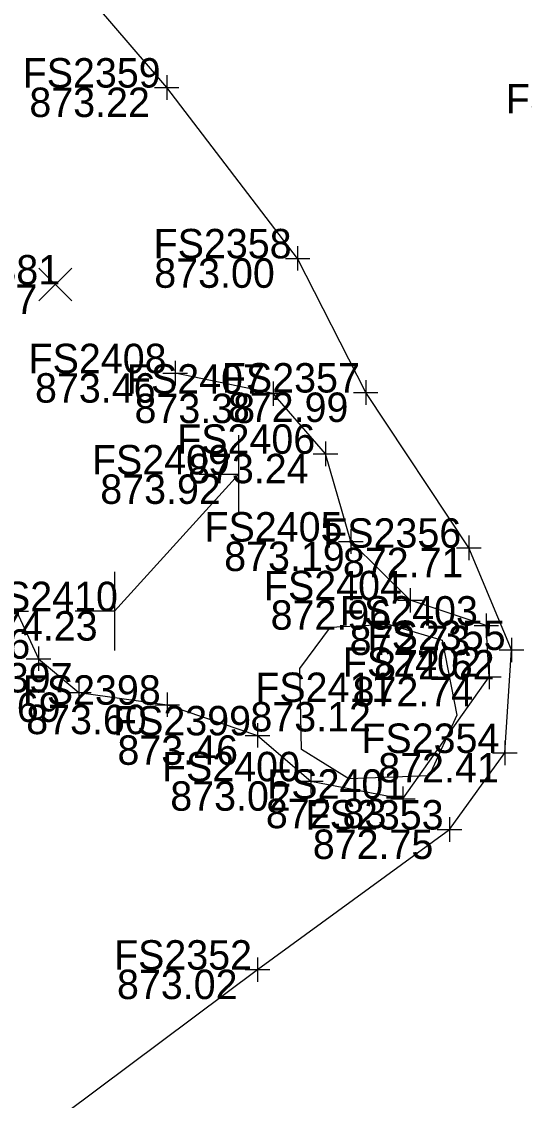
# Model space of a CAD drawing. Extents: x 1479420 to 1479833, y 379731 to 380103.
# Drawn here: x 1479533.91 to 1479554.39, y 379907.15 to 379951.11 of the extents above; entities that cross this region are included whole.
import ezdxf

# ---------------------------------------------------------------- set-up
doc = ezdxf.new("R2010")
doc.units = 0
for name, color, linetype in [('Default', 7, 'Continuous'), ('RD_X_Cells', 7, 'Continuous'), ('SN_X_Public', 7, 'Continuous'), ('SV_X_Break_Lines', 7, 'Continuous'), ('SV_X_Random_Point', 7, 'Continuous'), ('SV_X_Shot_Marker', 7, 'Continuous'), ('SV_X_Text_Elevation', 7, 'Continuous'), ('SV_X_Text_Name', 7, 'Continuous'), ('VG_X_Flower_Bed', 7, 'Continuous')]:
    doc.layers.add(name, color=color, linetype=linetype)

msp = doc.modelspace()

# ---------------------------------------------------------------- linework, layer by layer
at = {"layer": 'Default'}
msp.add_line((1479542.748, 379932.655), (1479537.693, 379927.083), dxfattribs=at)
at = {"layer": 'RD_X_Cells'}
msp.add_lwpolyline([(1479545.315, 379921.45), (1479545.24, 379924.75), (1479546.49, 379926.425), (1479548.84, 379926.55), (1479551.04, 379925.9), (1479551.64, 379922.85), (1479550.515, 379920.375), (1479547.24, 379920.25), (1479545.315, 379921.45)], dxfattribs=at)
at = {"layer": 'SN_X_Public'}
for p, q in [((1479542.748, 379934.255), (1479542.748, 379931.055)), ((1479542.748, 379932.655), (1479541.148, 379932.655)), ((1479537.693, 379928.683), (1479537.693, 379925.483)), ((1479537.693, 379927.083), (1479536.093, 379927.083))]:
    msp.add_line(p, q, dxfattribs=at)
at = {"layer": 'SV_X_Break_Lines'}
msp.add_lwpolyline([(1479534.387, 379905.648), (1479543.524, 379912.475), (1479551.336, 379918.185), (1479553.597, 379921.305), (1479553.861, 379925.501), (1479552.129, 379929.668), (1479547.926, 379935.993), (1479545.155, 379941.461), (1479539.822, 379948.42), (1479529.018, 379961.007), (1479520.635, 379970.728), (1479513.841, 379979.888), (1479504.809, 379988.776), (1479495.63, 379998.694), (1479487.89, 380006.933), (1479478.402, 380016.952), (1479472.872, 380022.536)], dxfattribs=at)
at = {"layer": 'SV_X_Random_Point'}
for p, q in [((1479534.619, 379939.728), (1479535.953, 379941.063)), ((1479534.619, 379941.063), (1479535.953, 379939.728))]:
    msp.add_line(p, q, dxfattribs=at)
at = {"layer": 'SV_X_Shot_Marker'}
for p, q in [((1479539.822, 379948.92), (1479539.822, 379947.92)), ((1479539.322, 379948.42), (1479540.322, 379948.42)), ((1479539.822, 379948.42), (1479539.822, 379948.42)), ((1479545.155, 379941.961), (1479545.155, 379940.961)), ((1479544.655, 379941.461), (1479545.655, 379941.461)), ((1479545.155, 379941.461), (1479545.155, 379941.461)), ((1479540.166, 379937.281), (1479540.166, 379936.281)), ((1479539.666, 379936.781), (1479540.666, 379936.781)), ((1479540.166, 379936.781), (1479540.166, 379936.781)), ((1479544.162, 379936.448), (1479544.162, 379935.448)), ((1479547.926, 379936.493), (1479547.926, 379935.493)), ((1479547.426, 379935.993), (1479548.426, 379935.993)), ((1479547.926, 379935.993), (1479547.926, 379935.993)), ((1479543.662, 379935.948), (1479544.662, 379935.948)), ((1479544.162, 379935.948), (1479544.162, 379935.948)), ((1479546.286, 379933.997), (1479546.286, 379932.997)), ((1479545.786, 379933.497), (1479546.786, 379933.497)), ((1479546.286, 379933.497), (1479546.286, 379933.497)), ((1479547.321, 379930.419), (1479547.321, 379929.419)), ((1479546.821, 379929.919), (1479547.821, 379929.919)), ((1479547.321, 379929.919), (1479547.321, 379929.919)), ((1479552.129, 379930.168), (1479552.129, 379929.168)), ((1479551.629, 379929.668), (1479552.629, 379929.668)), ((1479552.129, 379929.668), (1479552.129, 379929.668)), ((1479549.733, 379928.027), (1479549.733, 379927.027)), ((1479549.233, 379927.527), (1479550.233, 379927.527)), ((1479549.733, 379927.527), (1479549.733, 379927.527)), ((1479533.198, 379927.079), (1479534.198, 379927.079)), ((1479552.838, 379926.995), (1479552.838, 379925.995)), ((1479552.338, 379926.495), (1479553.338, 379926.495)), ((1479552.838, 379926.495), (1479552.838, 379926.495)), ((1479553.861, 379926.001), (1479553.861, 379925.001)), ((1479534.597, 379925.646), (1479534.597, 379924.646)), ((1479553.361, 379925.501), (1479554.361, 379925.501)), ((1479553.861, 379925.501), (1479553.861, 379925.501)), ((1479534.097, 379925.146), (1479535.097, 379925.146)), ((1479534.597, 379925.146), (1479534.597, 379925.146)), ((1479552.948, 379924.908), (1479552.948, 379923.908)), ((1479536.243, 379924.27), (1479536.243, 379923.27)), ((1479552.448, 379924.408), (1479553.448, 379924.408)), ((1479552.948, 379924.408), (1479552.948, 379924.408)), ((1479535.743, 379923.77), (1479536.743, 379923.77)), ((1479536.243, 379923.77), (1479536.243, 379923.77)), ((1479539.845, 379923.771), (1479539.845, 379922.771)), ((1479539.345, 379923.271), (1479540.345, 379923.271)), ((1479539.845, 379923.271), (1479539.845, 379923.271)), ((1479543.523, 379922.522), (1479543.523, 379921.522)), ((1479543.023, 379922.022), (1479544.023, 379922.022)), ((1479543.523, 379922.022), (1479543.523, 379922.022)), ((1479553.597, 379921.805), (1479553.597, 379920.805)), ((1479553.097, 379921.305), (1479554.097, 379921.305)), ((1479553.597, 379921.305), (1479553.597, 379921.305)), ((1479545.694, 379920.651), (1479545.694, 379919.651)), ((1479545.194, 379920.151), (1479546.194, 379920.151)), ((1479545.694, 379920.151), (1479545.694, 379920.151)), ((1479549.444, 379919.939), (1479549.444, 379918.939)), ((1479548.944, 379919.439), (1479549.944, 379919.439)), ((1479549.444, 379919.439), (1479549.444, 379919.439)), ((1479551.336, 379918.685), (1479551.336, 379917.685)), ((1479550.836, 379918.185), (1479551.836, 379918.185)), ((1479551.336, 379918.185), (1479551.336, 379918.185)), ((1479543.524, 379912.975), (1479543.524, 379911.975)), ((1479543.024, 379912.475), (1479544.024, 379912.475)), ((1479543.524, 379912.475), (1479543.524, 379912.475))]:
    msp.add_line(p, q, dxfattribs=at)
at = {"layer": 'VG_X_Flower_Bed'}
msp.add_lwpolyline([(1479533.698, 379927.079), (1479534.597, 379925.146), (1479536.243, 379923.77), (1479539.845, 379923.271), (1479543.523, 379922.022), (1479545.694, 379920.151), (1479549.444, 379919.439), (1479552.948, 379924.408), (1479552.838, 379926.495), (1479549.733, 379927.527), (1479547.321, 379929.919), (1479546.286, 379933.497), (1479544.162, 379935.948), (1479540.166, 379936.781)], dxfattribs=at)

# ---------------------------------------------------------------- texts
at = {"layer": 'SV_X_Text_Elevation'}
for s, p in [('873.22', (1479534.229, 379947.22)), ('873.00', (1479539.316, 379940.261)), ('873.67', (1479529.645, 379939.196)), ('873.46', (1479534.459, 379935.581)), ('872.99', (1479542.314, 379934.793)), ('873.38', (1479538.512, 379934.748)), ('873.24', (1479540.693, 379932.297)), ('873.92', (1479537.117, 379931.455)), ('873.19', (1479542.163, 379928.719)), ('872.71', (1479546.998, 379928.468)), ('872.96', (1479544.055, 379926.327)), ('874.23', (1479532.1, 379925.883)), ('872.73', (1479547.273, 379925.295)), ('872.62', (1479548.268, 379924.301)), ('872.74', (1479547.392, 379923.208)), ('873.69', (1479530.593, 379922.57)), ('873.60', (1479534.1, 379922.071)), ('873.12', (1479543.231, 379922.181)), ('873.46', (1479537.816, 379920.822)), ('872.41', (1479548.438, 379920.105)), ('873.02', (1479539.968, 379918.951)), ('872.83', (1479543.86, 379918.239)), ('872.75', (1479545.771, 379916.985)), ('873.02', (1479537.798, 379911.275))]:
    msp.add_text(s, height=1.2, dxfattribs=at).set_placement(p)
at = {"layer": 'SV_X_Text_Name'}
for s, p in [('FS2359', (1479533.955, 379948.42)), ('FS2445', (1479553.63, 379947.364)), ('FS2358', (1479539.288, 379941.461)), ('FS2381', (1479529.862, 379940.396)), ('FS2408', (1479534.195, 379936.781)), ('FS2407', (1479538.2, 379935.948)), ('FS2357', (1479542.068, 379935.993)), ('FS2406', (1479540.249, 379933.497)), ('FS2409', (1479536.777, 379932.655)), ('FS2405', (1479541.359, 379929.919)), ('FS2356', (1479546.196, 379929.668)), ('FS2404', (1479543.781, 379927.527)), ('FS2410', (1479532.214, 379927.083)), ('FS2403', (1479546.876, 379926.495)), ('FS2396', (1479528.645, 379925.146)), ('FS2355', (1479548.003, 379925.501)), ('FS2402', (1479546.996, 379924.408)), ('FS2397', (1479530.366, 379923.77)), ('FS2411', (1479543.429, 379923.381)), ('FS2398', (1479533.959, 379923.271)), ('FS2399', (1479537.637, 379922.022)), ('FS2354', (1479547.749, 379921.305)), ('FS2400', (1479539.628, 379920.151)), ('FS2401', (1479543.916, 379919.439)), ('FS2353', (1479545.478, 379918.185)), ('FS2352', (1479537.676, 379912.475))]:
    msp.add_text(s, height=1.2, dxfattribs=at).set_placement(p)

doc.saveas('drawing.dxf')
